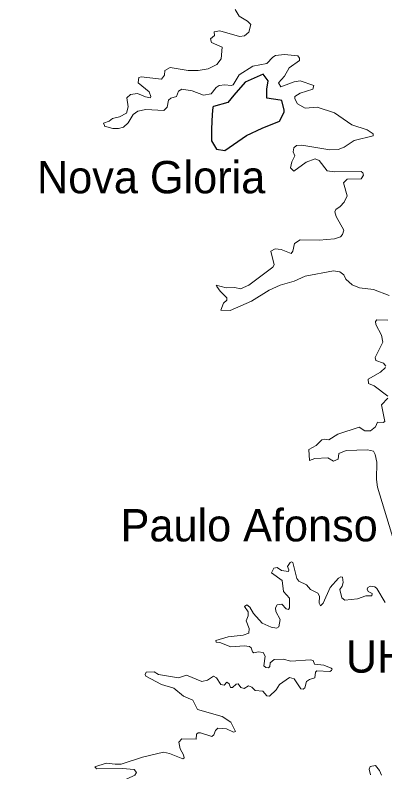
# Model space of a CAD drawing. Extents: x -1643653 to 4543381, y 1624270 to 13878484.
# Drawn here: x 578088 to 583806, y 8956904 to 8968607 of the extents above; entities that cross this region are included whole.
import ezdxf
from ezdxf.enums import TextEntityAlignment as Align

# ---------------------------------------------------------------- set-up
doc = ezdxf.new("R2010")
doc.units = 0
doc.header["$LTSCALE"] = 200
for name, color, linetype, lineweight in [('1', 7, 'Continuous', 13), ('21', 7, 'Continuous', 25), ('25', 7, 'Continuous', 13)]:
    doc.layers.add(name, color=color, linetype=linetype, lineweight=lineweight)
doc.layers.add('41', color=7, linetype='Continuous')
doc.layers.add('42', color=7, linetype='Continuous')

msp = doc.modelspace()

# ---------------------------------------------------------------- linework, layer by layer
at = {"layer": '1', "lineweight": 25}
msp.add_spline([(814781, 9009175.5), (814787.2, 9009173.4), (814796.9, 9009173.4), (814799.4, 9009172.4), (814805.1, 9009174.5), (814805.6, 9009176.5), (814811.7, 9009179.5), (814811.7, 9009179.5), (814801.5, 9009181), (814790.7, 9009181.5), (814784.1, 9009183.1), (814777.4, 9009185.1), (814778.4, 9009175.5)], degree=3, dxfattribs=at)
at = {"layer": '21'}
msp.add_lwpolyline([(581144.7, 8967182.6), (581135.4, 8967071.1), (581126.2, 8966848.2), (581126.2, 8966662.4), (581200.4, 8966532.3), (581330.4, 8966513.8), (581664.7, 8966746), (581906.1, 8966857.5), (582175.4, 8966968.9), (582249.7, 8967108.2), (582249.7, 8967136.1), (582212.6, 8967284.7), (582184.7, 8967294), (581980.4, 8967321.9), (581980.4, 8967461.2), (581999, 8967591.2), (581924.7, 8967693.4), (581646.1, 8967572.7), (581469.7, 8967368.3), (581376.9, 8967256.9), (581154, 8967191.8)], close=True, dxfattribs=at)
at = {"layer": '25'}
msp.add_line((579471.8, 8966890.6), (579467.6, 8966902.2), dxfattribs=at)
msp.add_line((579471.8, 8966890.6), (579467.6, 8966902.2), dxfattribs=at)
for points in [[(579997.9, 8967607), (580002.2, 8967641.4), (580036, 8967653.3), (580349.3, 8967615), (580399.9, 8967680.5), (580404.5, 8967748.8), (580485.3, 8967797.5), (580765.4, 8967750.9), (580918.4, 8967748.8), (581071.3, 8967774.2), (581209.4, 8967844.3), (581273.1, 8967931.4), (581290, 8968109.6), (581126.5, 8968182.3), (581109.5, 8968238.9), (581170.9, 8968290.2), (581167, 8968349.8), (581254, 8968362.6), (581560.2, 8968277.7), (581636.5, 8968288.5), (581702.2, 8968341.5), (581733.9, 8968462.6), (581683.1, 8968511.3), (581551.5, 8968590), (581492, 8968691.9)], [(579997.9, 8967607), (580002.2, 8967641.4), (580036, 8967653.3), (580349.3, 8967615), (580399.9, 8967680.5), (580404.5, 8967748.8), (580485.3, 8967797.5), (580765.4, 8967750.9), (580918.4, 8967748.8), (581071.3, 8967774.2), (581209.4, 8967844.3), (581273.1, 8967931.4), (581290, 8968109.6), (581126.5, 8968182.3), (581109.5, 8968238.9), (581170.9, 8968290.2), (581167, 8968349.8), (581254, 8968362.6), (581560.2, 8968277.7), (581636.5, 8968288.5), (581702.2, 8968341.5), (581733.9, 8968462.6), (581683.1, 8968511.3), (581551.5, 8968590), (581492, 8968691.9)], [(581209.9, 8964412.9), (581198.1, 8964430.9), (581351.7, 8964392.4), (581483.4, 8964396.6), (581572.4, 8964375.4), (581702.2, 8964430.7), (582073.9, 8964708.9), (582095.1, 8964745.1), (582044.3, 8964959.3), (582107.7, 8964995.5), (582107.7, 8964995.5), (582201.2, 8964983), (582356.2, 8964921.4), (582384.1, 8964957.7), (582407.6, 8965076.4), (582498.3, 8965133.6), (582792, 8965127.4), (583025.6, 8965146.5), (583119.2, 8965176.5), (583148.8, 8965212.4), (583170, 8965280.6), (583051.2, 8965492.5), (583034.2, 8965562.9), (583049.1, 8965601.1), (583114.8, 8965645.7), (583178, 8965717.2), (583225.2, 8965811.2), (583165.9, 8966013.2), (583223.5, 8966068.5), (583441.9, 8966077), (583475.9, 8966134.3), (583465.2, 8966170.4), (583439.6, 8966189.4), (583025.6, 8966183.2), (582915.7, 8966200), (582789.8, 8966359.4), (582728.2, 8966384.9), (582588.1, 8966331.8), (582396.7, 8966191.8), (582346, 8966247.1), (582364.9, 8966338), (582415.8, 8966429.6), (582390.2, 8966492.9), (582396.9, 8966552.7), (582441.5, 8966588.8), (582524.1, 8966597.4), (582953.4, 8966525.2), (583085.1, 8966527.3), (583178.8, 8966563.5), (583331.5, 8966667.5), (583624.5, 8966739.8), (583624.6, 8966771.3), (583531.2, 8966831), (583297.3, 8966909.8), (583025.6, 8967098.7), (582760.3, 8967185.7), (582571.1, 8967166.8), (582456.7, 8967236.5), (582416, 8967311.4), (582416.1, 8967347.1), (582494.8, 8967400.4), (582694, 8967461.9), (582706.9, 8967517.1), (582494.3, 8967589.4), (582401.1, 8967574.5), (582195.1, 8967498.2), (582159.1, 8967561.8), (582254.4, 8967663.6), (582326.8, 8967791.2), (582488.1, 8967904.1), (582488.1, 8967944.1), (582458.3, 8967980.2), (582256.4, 8967999.4), (582116.5, 8967984.5), (582071.9, 8967959), (581982.3, 8967861.3), (581763.8, 8967818.8), (581553.6, 8967684.9), (581459.8, 8967529.9), (581427.3, 8967517.2), (581332, 8967527.8), (581241.1, 8967517), (581198.8, 8967489.5), (581119.9, 8967389.7), (580998.9, 8967368.6), (580825.2, 8967438.5), (580667.5, 8967459.7), (580614.4, 8967431.8), (580582.4, 8967349.3), (580493.6, 8967323.8), (580457.7, 8967294.3), (580438.2, 8967185.8), (580385.3, 8967130.7), (580111.4, 8967147.6), (579983.5, 8967124), (579915.9, 8967069.1), (579835, 8966943.6), (579762.8, 8966875.7), (579686.3, 8966854.5), (579601.1, 8966852.3), (579471.8, 8966890.6)], [(581209.9, 8964412.9), (581198.1, 8964430.9), (581351.7, 8964392.4), (581483.4, 8964396.6), (581572.4, 8964375.4), (581702.2, 8964430.7), (582073.9, 8964708.9), (582095.1, 8964745.1), (582044.3, 8964959.3), (582107.7, 8964995.5), (582107.7, 8964995.5), (582201.2, 8964983), (582356.2, 8964921.4), (582384.1, 8964957.7), (582407.6, 8965076.4), (582498.3, 8965133.6), (582792, 8965127.4), (583025.6, 8965146.5), (583119.2, 8965176.5), (583148.8, 8965212.4), (583170, 8965280.6), (583051.2, 8965492.5), (583034.2, 8965562.9), (583049.1, 8965601.1), (583114.8, 8965645.7), (583178, 8965717.2), (583225.2, 8965811.2), (583165.9, 8966013.2), (583223.5, 8966068.5), (583441.9, 8966077), (583475.9, 8966134.3), (583465.2, 8966170.4), (583439.6, 8966189.4), (583025.6, 8966183.2), (582915.7, 8966200), (582789.8, 8966359.4), (582728.2, 8966384.9), (582588.1, 8966331.8), (582396.7, 8966191.8), (582346, 8966247.1), (582364.9, 8966338), (582415.8, 8966429.6), (582390.2, 8966492.9), (582396.9, 8966552.7), (582441.5, 8966588.8), (582524.1, 8966597.4), (582953.4, 8966525.2), (583085.1, 8966527.3), (583178.8, 8966563.5), (583331.5, 8966667.5), (583624.5, 8966739.8), (583624.6, 8966771.3), (583531.2, 8966831), (583297.3, 8966909.8), (583025.6, 8967098.7), (582760.3, 8967185.7), (582571.1, 8967166.8), (582456.7, 8967236.5), (582416, 8967311.4), (582416.1, 8967347.1), (582494.8, 8967400.4), (582694, 8967461.9), (582706.9, 8967517.1), (582494.3, 8967589.4), (582401.1, 8967574.5), (582195.1, 8967498.2), (582159.1, 8967561.8), (582254.4, 8967663.6), (582326.8, 8967791.2), (582488.1, 8967904.1), (582488.1, 8967944.1), (582458.3, 8967980.2), (582256.4, 8967999.4), (582116.5, 8967984.5), (582071.9, 8967959), (581982.3, 8967861.3), (581763.8, 8967818.8), (581553.6, 8967684.9), (581459.8, 8967529.9), (581427.3, 8967517.2), (581332, 8967527.8), (581241.1, 8967517), (581198.8, 8967489.5), (581119.9, 8967389.7), (580998.9, 8967368.6), (580825.2, 8967438.5), (580667.5, 8967459.7), (580614.4, 8967431.8), (580582.4, 8967349.3), (580493.6, 8967323.8), (580457.7, 8967294.3), (580438.2, 8967185.8), (580385.3, 8967130.7), (580111.4, 8967147.6), (579983.5, 8967124), (579915.9, 8967069.1), (579835, 8966943.6), (579762.8, 8966875.7), (579686.3, 8966854.5), (579601.1, 8966852.3), (579471.8, 8966890.6)], [(579467.6, 8966902.2), (579455.3, 8966936.2), (579541.6, 8966967.5), (579595, 8967007.3), (579704, 8967033.2), (579811.7, 8967092.6), (579835, 8967188.5), (579813.9, 8967330.2), (579873.1, 8967378.9), (579979.2, 8967396.1), (580105, 8967343), (580105, 8967343), (580181.1, 8967330.4), (580187.4, 8967349.7), (580161, 8967421.7), (579992.3, 8967561.8), (579997.9, 8967607)], [(579467.6, 8966902.2), (579455.3, 8966936.2), (579541.6, 8966967.5), (579595, 8967007.3), (579704, 8967033.2), (579811.7, 8967092.6), (579835, 8967188.5), (579813.9, 8967330.2), (579873.1, 8967378.9), (579979.2, 8967396.1), (580105, 8967343), (580105, 8967343), (580181.1, 8967330.4), (580187.4, 8967349.7), (580161, 8967421.7), (579992.3, 8967561.8), (579997.9, 8967607)], [(583013.2, 8964651.5), (582571.3, 8964568.8), (582405.6, 8964492.4), (582184.7, 8964432.8), (582018.8, 8964356.3), (581742.6, 8964184.2), (581411.2, 8964039.8), (581271.6, 8964044.5), (581311.5, 8964150.2), (581362.2, 8964201), (581362.3, 8964235), (581258.4, 8964339.1), (581209.9, 8964412.9)], [(583013.2, 8964651.5), (582571.3, 8964568.8), (582405.6, 8964492.4), (582184.7, 8964432.8), (582018.8, 8964356.3), (581742.6, 8964184.2), (581411.2, 8964039.8), (581271.6, 8964044.5), (581311.5, 8964150.2), (581362.2, 8964201), (581362.3, 8964235), (581258.4, 8964339.1), (581209.9, 8964412.9)], [(583871.3, 8964269), (583632.9, 8964364.8), (583412.2, 8964392.4), (583302.1, 8964434.8), (583202.2, 8964526), (583174.1, 8964592.2), (583110.6, 8964638.7), (583013.2, 8964651.5)], [(583871.3, 8964269), (583632.9, 8964364.8), (583412.2, 8964392.4), (583302.1, 8964434.8), (583202.2, 8964526), (583174.1, 8964592.2), (583110.6, 8964638.7), (583013.2, 8964651.5)], [(583820, 8963181), (583784.2, 8963226), (583667.3, 8963264.5), (583654.7, 8963312.4), (583773.3, 8963547.2), (583756.3, 8963657.4), (583667.3, 8963822.9), (583661, 8963870), (583680, 8963897.4), (583854.1, 8963889)], [(583820, 8963181), (583784.2, 8963226), (583667.3, 8963264.5), (583654.7, 8963312.4), (583773.3, 8963547.2), (583756.3, 8963657.4), (583667.3, 8963822.9), (583661, 8963870), (583680, 8963897.4), (583854.1, 8963889)], [(583854, 8962716.3), (583639.8, 8962873.4), (583552.7, 8962911.8), (583548.2, 8962977.4), (583737.5, 8963086.2), (583815.2, 8963159.7)], [(583854, 8962716.3), (583639.8, 8962873.4), (583552.7, 8962911.8), (583548.2, 8962977.4), (583737.5, 8963086.2), (583815.2, 8963159.7)], [(583979.3, 8960356.6), (583690.5, 8961308.2), (583675.7, 8961427), (583679.9, 8961694.8), (583656.7, 8961812.9), (583631.9, 8961861.4), (583535.2, 8961883.6), (583208.6, 8961873.1), (583093.8, 8961826.3), (583082.9, 8961741.4), (583013.1, 8961707.5), (582923.6, 8961760.4), (582724.2, 8961752), (582642.1, 8961718.4), (582632.6, 8961889.8), (582741.2, 8961953.9), (582832.4, 8962038.7), (582866.3, 8962051.4), (582940.9, 8962038.9), (583076.4, 8962125.7), (583410.3, 8962234), (583497.2, 8962176.9), (583584.3, 8962176.9), (583662.8, 8962238.5), (583692.8, 8962310.5), (583781.6, 8962306.4), (583807.2, 8962323.5), (583752.2, 8962580.2), (583853.2, 8962685.6)], [(583979.3, 8960356.6), (583690.5, 8961308.2), (583675.7, 8961427), (583679.9, 8961694.8), (583656.7, 8961812.9), (583631.9, 8961861.4), (583535.2, 8961883.6), (583208.6, 8961873.1), (583093.8, 8961826.3), (583082.9, 8961741.4), (583013.1, 8961707.5), (582923.6, 8961760.4), (582724.2, 8961752), (582642.1, 8961718.4), (582632.6, 8961889.8), (582741.2, 8961953.9), (582832.4, 8962038.7), (582866.3, 8962051.4), (582940.9, 8962038.9), (583076.4, 8962125.7), (583410.3, 8962234), (583497.2, 8962176.9), (583584.3, 8962176.9), (583662.8, 8962238.5), (583692.8, 8962310.5), (583781.6, 8962306.4), (583807.2, 8962323.5), (583752.2, 8962580.2), (583853.2, 8962685.6)], [(582299.4, 8960082.5), (582339.6, 8960143.8), (582362.8, 8960152.2), (582381.9, 8960139.6), (582443.6, 8959893.3), (582477.6, 8959853), (582596.3, 8959797.7), (582656.1, 8959725.5), (582771.8, 8959670.2), (582795.6, 8959619.4), (582792, 8959510.9), (582809, 8959470.7), (582851.4, 8959515.1), (582957.8, 8959753.2), (583089.5, 8959901.9), (583125.3, 8959922.9), (583148.8, 8959914.2), (583159.4, 8959833.8), (583144.6, 8959774.5), (583108.6, 8959723.3), (583108.6, 8959723.3), (583138.3, 8959595.9), (583184.5, 8959559.9), (583382, 8959578.8), (583514.4, 8959627.7), (583603.4, 8959628), (583607.5, 8959661.8), (583550.2, 8959691.6), (583531.3, 8959731.8), (583541.6, 8959757), (583580.3, 8959774.3), (583651.7, 8959765.9), (583684, 8959740.2), (583809.5, 8959521.5)], [(582299.4, 8960082.5), (582339.6, 8960143.8), (582362.8, 8960152.2), (582381.9, 8960139.6), (582443.6, 8959893.3), (582477.6, 8959853), (582596.3, 8959797.7), (582656.1, 8959725.5), (582771.8, 8959670.2), (582795.6, 8959619.4), (582792, 8959510.9), (582809, 8959470.7), (582851.4, 8959515.1), (582957.8, 8959753.2), (583089.5, 8959901.9), (583125.3, 8959922.9), (583148.8, 8959914.2), (583159.4, 8959833.8), (583144.6, 8959774.5), (583108.6, 8959723.3), (583108.6, 8959723.3), (583138.3, 8959595.9), (583184.5, 8959559.9), (583382, 8959578.8), (583514.4, 8959627.7), (583603.4, 8959628), (583607.5, 8959661.8), (583550.2, 8959691.6), (583531.3, 8959731.8), (583541.6, 8959757), (583580.3, 8959774.3), (583651.7, 8959765.9), (583684, 8959740.2), (583809.5, 8959521.5)], [(580099.6, 8958407.9), (580098.5, 8958410.3), (580113.2, 8958444.3), (580235.9, 8958453.9), (580303, 8958410.4), (580612.5, 8958359.6), (580740.2, 8958401.9), (580973.9, 8958304.4), (581064.7, 8958323.4), (581156.5, 8958384.9), (581203.2, 8958359.3), (581270.9, 8958257.8), (581319.8, 8958245), (581360.2, 8958291.4), (581400.5, 8958268.1), (581420.4, 8958210.8), (581447.3, 8958208.8), (581504.7, 8958259.6), (581539.6, 8958263.8), (581539.6, 8958263.8), (581578.9, 8958209), (581627.9, 8958191.9), (581696, 8958236.1), (581748.9, 8958212.8), (581799.4, 8958164.3), (581920, 8958154), (581978.5, 8958081.4), (582019.4, 8958072.8), (582127.2, 8958170.8), (582178.1, 8958253.3), (582332.9, 8958361.5), (582401, 8958344.6), (582505.1, 8958189.8), (582543.4, 8958185.4), (582568.8, 8958204.3), (582596.6, 8958300), (582641.2, 8958331.9), (582721.7, 8958357.6), (582732.5, 8958448.5), (582755.7, 8958467.7), (582953.2, 8958455.2), (582983.1, 8958470.1), (582989.4, 8958491.2), (582974.4, 8958510.4), (582859.9, 8958554.9), (582719.7, 8958570.1), (582696.2, 8958625.2), (582656.2, 8958635.6), (582353.6, 8958614.5), (582235.7, 8958646.3), (582095.5, 8958639.9), (582031.7, 8958591.2), (582027, 8958531.6), (582005.7, 8958514.7), (581967.3, 8958516.9), (581933.7, 8958544.9), (581955, 8958692.5), (581922.9, 8958748.3), (581848.8, 8958761), (581780.6, 8958746.3), (581757.5, 8958761.1), (581738.2, 8958822.6), (581712.6, 8958841.7), (581627.9, 8958854.5), (581424.2, 8958839.7), (581251.8, 8958907.5), (581194.6, 8958907.9), (581190.6, 8958937.3), (581381.2, 8958994.6), (581615.1, 8959015.9), (581699.9, 8959047.7), (581708.6, 8959122.1), (581659.8, 8959239), (581692.1, 8959315.5), (581691.6, 8959378.9), (581634.5, 8959460), (581670.4, 8959485.2), (581717.2, 8959451.2), (581774.6, 8959353.5), (581908.3, 8959202.9), (582046.5, 8959141.3), (582129.4, 8959128.6), (582167.3, 8959147.5), (582188.6, 8959260.2), (582118.7, 8959385.4), (582116.5, 8959440.5), (582142.1, 8959487.4), (582214.1, 8959495.9), (582278, 8959423.9), (582316.1, 8959415.5), (582331, 8959439.1), (582330.8, 8959589.7), (582237.6, 8959695.7), (582220.4, 8959865.6), (582050.7, 8959980.4), (582091.2, 8960052.6), (582141.7, 8960063.2), (582208.1, 8960016.5), (582315.9, 8960001.7), (582322.5, 8960029), (582299.4, 8960082.5)], [(580099.6, 8958407.9), (580098.5, 8958410.3), (580113.2, 8958444.3), (580235.9, 8958453.9), (580303, 8958410.4), (580612.5, 8958359.6), (580740.2, 8958401.9), (580973.9, 8958304.4), (581064.7, 8958323.4), (581156.5, 8958384.9), (581203.2, 8958359.3), (581270.9, 8958257.8), (581319.8, 8958245), (581360.2, 8958291.4), (581400.5, 8958268.1), (581420.4, 8958210.8), (581447.3, 8958208.8), (581504.7, 8958259.6), (581539.6, 8958263.8), (581539.6, 8958263.8), (581578.9, 8958209), (581627.9, 8958191.9), (581696, 8958236.1), (581748.9, 8958212.8), (581799.4, 8958164.3), (581920, 8958154), (581978.5, 8958081.4), (582019.4, 8958072.8), (582127.2, 8958170.8), (582178.1, 8958253.3), (582332.9, 8958361.5), (582401, 8958344.6), (582505.1, 8958189.8), (582543.4, 8958185.4), (582568.8, 8958204.3), (582596.6, 8958300), (582641.2, 8958331.9), (582721.7, 8958357.6), (582732.5, 8958448.5), (582755.7, 8958467.7), (582953.2, 8958455.2), (582983.1, 8958470.1), (582989.4, 8958491.2), (582974.4, 8958510.4), (582859.9, 8958554.9), (582719.7, 8958570.1), (582696.2, 8958625.2), (582656.2, 8958635.6), (582353.6, 8958614.5), (582235.7, 8958646.3), (582095.5, 8958639.9), (582031.7, 8958591.2), (582027, 8958531.6), (582005.7, 8958514.7), (581967.3, 8958516.9), (581933.7, 8958544.9), (581955, 8958692.5), (581922.9, 8958748.3), (581848.8, 8958761), (581780.6, 8958746.3), (581757.5, 8958761.1), (581738.2, 8958822.6), (581712.6, 8958841.7), (581627.9, 8958854.5), (581424.2, 8958839.7), (581251.8, 8958907.5), (581194.6, 8958907.9), (581190.6, 8958937.3), (581381.2, 8958994.6), (581615.1, 8959015.9), (581699.9, 8959047.7), (581708.6, 8959122.1), (581659.8, 8959239), (581692.1, 8959315.5), (581691.6, 8959378.9), (581634.5, 8959460), (581670.4, 8959485.2), (581717.2, 8959451.2), (581774.6, 8959353.5), (581908.3, 8959202.9), (582046.5, 8959141.3), (582129.4, 8959128.6), (582167.3, 8959147.5), (582188.6, 8959260.2), (582118.7, 8959385.4), (582116.5, 8959440.5), (582142.1, 8959487.4), (582214.1, 8959495.9), (582278, 8959423.9), (582316.1, 8959415.5), (582331, 8959439.1), (582330.8, 8959589.7), (582237.6, 8959695.7), (582220.4, 8959865.6), (582050.7, 8959980.4), (582091.2, 8960052.6), (582141.7, 8960063.2), (582208.1, 8960016.5), (582315.9, 8960001.7), (582322.5, 8960029), (582299.4, 8960082.5)], [(579330.4, 8956970.9), (579320.1, 8956982.2), (579494.9, 8957040.3), (579635.1, 8957021.3), (579729, 8957025.6), (580056.8, 8957131.9), (580383.3, 8957210.3), (580477.4, 8957190.9), (580682.8, 8957104.2), (580701.6, 8957122.8), (580693.2, 8957169.7), (580640, 8957259.4), (580619.2, 8957363.6), (580667.8, 8957416.2), (580886.3, 8957410), (580890.9, 8957486.6), (580919.1, 8957507.7), (580955.2, 8957509.6), (581130.8, 8957450.5), (581162.8, 8957476.1), (581188.5, 8957544.2), (581224.5, 8957577.8), (581357.9, 8957571.4), (581466.2, 8957520.6), (581496, 8957526.9), (581421.8, 8957673.3), (581289.9, 8957760.6), (580910.1, 8957870.9), (580835.5, 8958013.2), (580692.5, 8958073.2), (580540.2, 8958198), (580349.1, 8958255.5), (580111.4, 8958382.8), (580099.6, 8958407.9)], [(579330.4, 8956970.9), (579320.1, 8956982.2), (579494.9, 8957040.3), (579635.1, 8957021.3), (579729, 8957025.6), (580056.8, 8957131.9), (580383.3, 8957210.3), (580477.4, 8957190.9), (580682.8, 8957104.2), (580701.6, 8957122.8), (580693.2, 8957169.7), (580640, 8957259.4), (580619.2, 8957363.6), (580667.8, 8957416.2), (580886.3, 8957410), (580890.9, 8957486.6), (580919.1, 8957507.7), (580955.2, 8957509.6), (581130.8, 8957450.5), (581162.8, 8957476.1), (581188.5, 8957544.2), (581224.5, 8957577.8), (581357.9, 8957571.4), (581466.2, 8957520.6), (581496, 8957526.9), (581421.8, 8957673.3), (581289.9, 8957760.6), (580910.1, 8957870.9), (580835.5, 8958013.2), (580692.5, 8958073.2), (580540.2, 8958198), (580349.1, 8958255.5), (580111.4, 8958382.8), (580099.6, 8958407.9)], [(579269.2, 8956128.5), (579267.5, 8956147.6), (579346.5, 8956275.5), (579569.6, 8956488.2), (579763, 8956751.6), (579818, 8956796.1), (579936.8, 8956853.3), (579964.5, 8956895.9), (579931, 8956942.9), (579750.3, 8956955.4), (579346.5, 8956953.4), (579330.4, 8956970.9)], [(579269.2, 8956128.5), (579267.5, 8956147.6), (579346.5, 8956275.5), (579569.6, 8956488.2), (579763, 8956751.6), (579818, 8956796.1), (579936.8, 8956853.3), (579964.5, 8956895.9), (579931, 8956942.9), (579750.3, 8956955.4), (579346.5, 8956953.4), (579330.4, 8956970.9)], [(583756.3, 8956851.3), (583724.4, 8956925.6), (583660.8, 8957002.1), (583580.2, 8956987.2), (583561.1, 8956946.9), (583586.5, 8956859.9)], [(583756.3, 8956851.3), (583724.4, 8956925.6), (583660.8, 8957002.1), (583580.2, 8956987.2), (583561.1, 8956946.9), (583586.5, 8956859.9)]]:
    msp.add_lwpolyline(points, dxfattribs=at)

# ---------------------------------------------------------------- texts
at = {"layer": '41'}
for s, p in [('Nova Gloria', (580191.1, 8965851.8)), ('Paulo Afonso', (581707.6, 8960468.8))]:
    msp.add_text(s, height=500, dxfattribs=at).set_placement(p, align=Align.CENTER)
at = {"layer": '42'}
msp.add_text('UHE PA IV', height=500, dxfattribs=at).set_placement((584857.3, 8958438.7), align=Align.CENTER)

doc.saveas('drawing.dxf')
